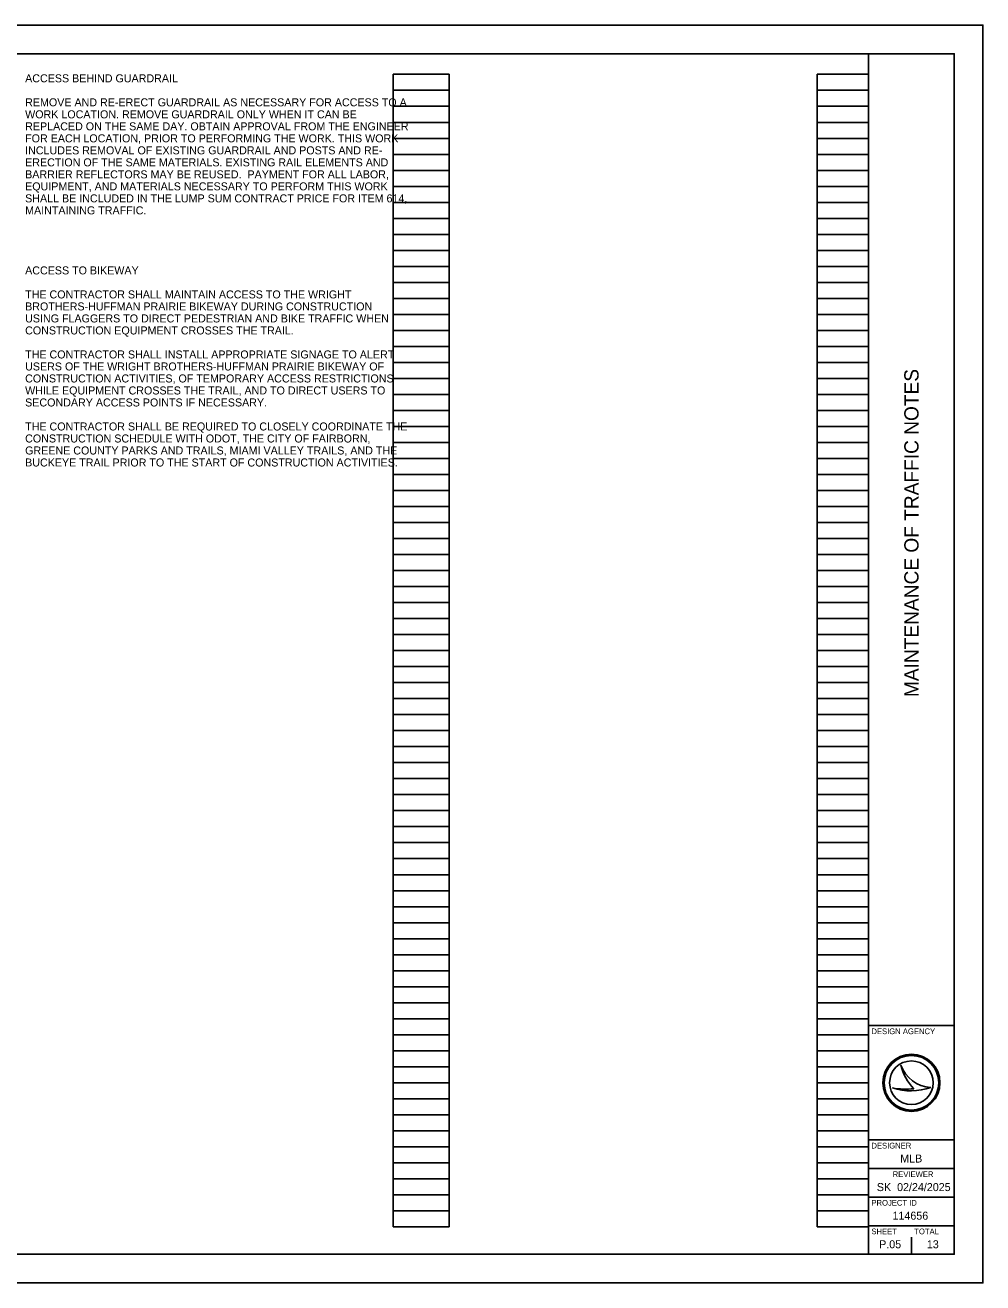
# Model space of a CAD drawing. Extents: x 0 to 34, y 0 to 22.
# Drawn here: x 17.24 to 34, y 0 to 22 of the extents above; entities that cross this region are included whole.
import ezdxf

# ---------------------------------------------------------------- set-up
doc = ezdxf.new("R2010")
doc.units = 0
for name, color, linetype in [('SH_Border', 7, 'Continuous'), ('SH_Cut_Line', 7, 'Continuous'), ('SH_Data', 7, 'Continuous'), ('SH_Text', 7, 'Continuous')]:
    doc.layers.add(name, color=color, linetype=linetype)

msp = doc.modelspace()

# ---------------------------------------------------------------- linework, layer by layer
at = {"layer": 'SH_Border'}
for p, q in [((32, 0.5), (32, 21.5)), ((32, 4.5), (33.5, 4.5)), ((32, 2.5), (33.5, 2.5)), ((32, 2), (33.5, 2)), ((32, 1.5), (33.5, 1.5)), ((32, 1), (33.5, 1))]:
    msp.add_line(p, q, dxfattribs=at)
msp.add_lwpolyline([(1.5, 21.5), (33.5, 21.5), (33.5, 0.5), (1.5, 0.5)], close=True, dxfattribs=at)
at = {"layer": 'SH_Cut_Line'}
msp.add_lwpolyline([(0, 0), (34, 0), (34, 22), (0, 22)], close=True, dxfattribs=at)
at = {"layer": 'SH_Data'}
for p, q in [((23.68, 0.98), (23.68, 21.14)), ((23.68, 21.14), (24.66, 21.14)), ((24.66, 0.98), (24.66, 21.14)), ((31.1, 0.98), (31.1, 21.14)), ((31.1, 21.14), (32, 21.14)), ((32, 0.98), (32, 21.14)), ((23.68, 20.86), (24.66, 20.86)), ((31.1, 20.86), (32, 20.86)), ((23.68, 20.58), (24.66, 20.58)), ((31.1, 20.58), (32, 20.58)), ((23.68, 20.3), (24.66, 20.3)), ((31.1, 20.3), (32, 20.3)), ((23.68, 20.02), (24.66, 20.02)), ((31.1, 20.02), (32, 20.02)), ((23.68, 19.74), (24.66, 19.74)), ((31.1, 19.74), (32, 19.74)), ((23.68, 19.46), (24.66, 19.46)), ((31.1, 19.46), (32, 19.46)), ((23.68, 19.18), (24.66, 19.18)), ((31.1, 19.18), (32, 19.18)), ((23.68, 18.9), (24.66, 18.9)), ((31.1, 18.9), (32, 18.9)), ((23.68, 18.62), (24.66, 18.62)), ((31.1, 18.62), (32, 18.62)), ((23.68, 18.34), (24.66, 18.34)), ((31.1, 18.34), (32, 18.34)), ((23.68, 18.06), (24.66, 18.06)), ((31.1, 18.06), (32, 18.06)), ((23.68, 17.78), (24.66, 17.78)), ((31.1, 17.78), (32, 17.78)), ((23.68, 17.5), (24.66, 17.5)), ((31.1, 17.5), (32, 17.5)), ((23.68, 17.22), (24.66, 17.22)), ((31.1, 17.22), (32, 17.22)), ((23.68, 16.94), (24.66, 16.94)), ((31.1, 16.94), (32, 16.94)), ((23.68, 16.66), (24.66, 16.66)), ((31.1, 16.66), (32, 16.66)), ((23.68, 16.38), (24.66, 16.38)), ((31.1, 16.38), (32, 16.38)), ((23.68, 16.1), (24.66, 16.1)), ((31.1, 16.1), (32, 16.1)), ((23.68, 15.82), (24.66, 15.82)), ((31.1, 15.82), (32, 15.82)), ((23.68, 15.54), (24.66, 15.54)), ((31.1, 15.54), (32, 15.54)), ((23.68, 15.26), (24.66, 15.26)), ((31.1, 15.26), (32, 15.26)), ((23.68, 14.98), (24.66, 14.98)), ((31.1, 14.98), (32, 14.98)), ((23.68, 14.7), (24.66, 14.7)), ((31.1, 14.7), (32, 14.7)), ((23.68, 14.42), (24.66, 14.42)), ((31.1, 14.42), (32, 14.42)), ((23.68, 14.14), (24.66, 14.14)), ((31.1, 14.14), (32, 14.14)), ((23.68, 13.86), (24.66, 13.86)), ((31.1, 13.86), (32, 13.86)), ((23.68, 13.58), (24.66, 13.58)), ((31.1, 13.58), (32, 13.58)), ((23.68, 13.3), (24.66, 13.3)), ((31.1, 13.3), (32, 13.3)), ((23.68, 13.02), (24.66, 13.02)), ((31.1, 13.02), (32, 13.02)), ((23.68, 12.74), (24.66, 12.74)), ((31.1, 12.74), (32, 12.74)), ((23.68, 12.46), (24.66, 12.46)), ((31.1, 12.46), (32, 12.46)), ((23.68, 12.18), (24.66, 12.18)), ((31.1, 12.18), (32, 12.18)), ((23.68, 11.9), (24.66, 11.9)), ((31.1, 11.9), (32, 11.9)), ((23.68, 11.62), (24.66, 11.62)), ((31.1, 11.62), (32, 11.62)), ((23.68, 11.34), (24.66, 11.34)), ((31.1, 11.34), (32, 11.34)), ((23.68, 11.06), (24.66, 11.06)), ((31.1, 11.06), (32, 11.06)), ((23.68, 10.78), (24.66, 10.78)), ((31.1, 10.78), (32, 10.78)), ((23.68, 10.5), (24.66, 10.5)), ((31.1, 10.5), (32, 10.5)), ((23.68, 10.22), (24.66, 10.22)), ((31.1, 10.22), (32, 10.22)), ((23.68, 9.94), (24.66, 9.94)), ((31.1, 9.94), (32, 9.94)), ((23.68, 9.66), (24.66, 9.66)), ((31.1, 9.66), (32, 9.66)), ((23.68, 9.38), (24.66, 9.38)), ((31.1, 9.38), (32, 9.38)), ((23.68, 9.1), (24.66, 9.1)), ((31.1, 9.1), (32, 9.1)), ((23.68, 8.82), (24.66, 8.82)), ((31.1, 8.82), (32, 8.82)), ((23.68, 8.54), (24.66, 8.54)), ((31.1, 8.54), (32, 8.54)), ((23.68, 8.26), (24.66, 8.26)), ((31.1, 8.26), (32, 8.26)), ((23.68, 7.98), (24.66, 7.98)), ((31.1, 7.98), (32, 7.98)), ((23.68, 7.7), (24.66, 7.7)), ((31.1, 7.7), (32, 7.7)), ((23.68, 7.42), (24.66, 7.42)), ((31.1, 7.42), (32, 7.42)), ((23.68, 7.14), (24.66, 7.14)), ((31.1, 7.14), (32, 7.14)), ((23.68, 6.86), (24.66, 6.86)), ((31.1, 6.86), (32, 6.86)), ((23.68, 6.58), (24.66, 6.58)), ((31.1, 6.58), (32, 6.58)), ((23.68, 6.3), (24.66, 6.3)), ((31.1, 6.3), (32, 6.3)), ((23.68, 6.02), (24.66, 6.02)), ((31.1, 6.02), (32, 6.02)), ((23.68, 5.74), (24.66, 5.74)), ((31.1, 5.74), (32, 5.74)), ((23.68, 5.46), (24.66, 5.46)), ((31.1, 5.46), (32, 5.46)), ((23.68, 5.18), (24.66, 5.18)), ((31.1, 5.18), (32, 5.18)), ((23.68, 4.9), (24.66, 4.9)), ((31.1, 4.9), (32, 4.9)), ((23.68, 4.62), (24.66, 4.62)), ((31.1, 4.62), (32, 4.62)), ((23.68, 4.34), (24.66, 4.34)), ((31.1, 4.34), (32, 4.34)), ((23.68, 4.06), (24.66, 4.06)), ((31.1, 4.06), (32, 4.06)), ((23.68, 3.78), (24.66, 3.78)), ((31.1, 3.78), (32, 3.78)), ((32.567, 3.81), (32.567, 3.81)), ((23.68, 3.5), (24.66, 3.5)), ((31.1, 3.5), (32, 3.5)), ((32.417, 3.41), (32.417, 3.41)), ((32.75, 3.5), (32.75, 3.5)), ((33.087, 3.419), (33.087, 3.419)), ((23.68, 3.22), (24.66, 3.22)), ((31.1, 3.22), (32, 3.22)), ((23.68, 2.94), (24.66, 2.94)), ((31.1, 2.94), (32, 2.94)), ((23.68, 2.66), (24.66, 2.66)), ((31.1, 2.66), (32, 2.66)), ((23.68, 2.38), (24.66, 2.38)), ((31.1, 2.38), (32, 2.38)), ((23.68, 2.1), (24.66, 2.1)), ((31.1, 2.1), (32, 2.1)), ((23.68, 1.82), (24.66, 1.82)), ((31.1, 1.82), (32, 1.82)), ((23.68, 1.54), (24.66, 1.54)), ((31.1, 1.54), (32, 1.54)), ((23.68, 1.26), (24.66, 1.26)), ((31.1, 1.26), (32, 1.26)), ((23.68, 0.98), (24.66, 0.98)), ((31.1, 0.98), (32, 0.98)), ((32.375, 0.675), (32.375, 0.675)), ((32.75, 0.5), (32.75, 0.8))]:
    msp.add_line(p, q, dxfattribs=at)
for radius in [0.5, 0.477, 0.477, 0.382]:
    msp.add_circle((32.75, 3.5), radius, dxfattribs=at)
for centre, radius, start, end in [((33.116, 3.998), 0.58, 198.9257, 198.9319), ((33.347, 3.97), 0.796, 191.6379, 191.6421), ((33.116, 3.998), 0.58, 198.9319, 267.1657), ((33.347, 3.97), 0.796, 191.6421, 226.0947), ((32.739, 4.37), 1.013, 251.4576, 290.0832), ((32.648, 4.654), 1.266, 259.4964, 259.4995), ((32.739, 4.37), 1.013, 251.4527, 251.4576), ((32.648, 4.654), 1.266, 259.4995, 276.6672)]:
    msp.add_arc(centre, radius, start, end, dxfattribs=at)

# ---------------------------------------------------------------- texts
msp.add_text('MAINTENANCE OF TRAFFIC NOTES', height=0.25, rotation=90, dxfattribs=at).set_placement((32.875, 10.247))
for s, height, p in [('DESIGN AGENCY', 0.1, (32.05, 4.35)), ('DESIGNER', 0.1, (32.05, 2.35)), ('MLB', 0.14, (32.554, 2.105)), ('REVIEWER', 0.1, (32.422, 1.85)), ('SK', 0.14, (32.145, 1.605)), ('02/24/2025', 0.14, (32.499, 1.605)), ('PROJECT ID', 0.1, (32.05, 1.35)), ('114656', 0.14, (32.419, 1.105)), ('SHEET', 0.1, (32.05, 0.85)), ('TOTAL', 0.1, (32.8, 0.85)), ('P.05', 0.14, (32.185, 0.605)), ('13', 0.14, (33.02, 0.605))]:
    msp.add_text(s, height=height, dxfattribs=at).set_placement(p)
at = {"layer": 'SH_Text'}
for s, p in [('ACCESS BEHIND GUARDRAIL', (17.24, 21)), ('REMOVE AND RE-ERECT GUARDRAIL AS NECESSARY FOR ACCESS TO A ', (17.24, 20.58)), ('WORK LOCATION. REMOVE GUARDRAIL ONLY WHEN IT CAN BE ', (17.24, 20.37)), ('REPLACED ON THE SAME DAY. OBTAIN APPROVAL FROM THE ENGINEER ', (17.24, 20.16)), ('FOR EACH LOCATION, PRIOR TO PERFORMING THE WORK. THIS WORK ', (17.24, 19.95)), ('INCLUDES REMOVAL OF EXISTING GUARDRAIL AND POSTS AND RE-', (17.24, 19.74)), ('ERECTION OF THE SAME MATERIALS. EXISTING RAIL ELEMENTS AND ', (17.24, 19.53)), ('BARRIER REFLECTORS MAY BE REUSED.  PAYMENT FOR ALL LABOR, ', (17.24, 19.32)), ('EQUIPMENT, AND MATERIALS NECESSARY TO PERFORM THIS WORK ', (17.24, 19.11)), ('SHALL BE INCLUDED IN THE LUMP SUM CONTRACT PRICE FOR ITEM 614, ', (17.24, 18.9)), ('MAINTAINING TRAFFIC.', (17.24, 18.69)), ('ACCESS TO BIKEWAY', (17.24, 17.64)), ('THE CONTRACTOR SHALL MAINTAIN ACCESS TO THE WRIGHT ', (17.24, 17.22)), ('USING FLAGGERS TO DIRECT PEDESTRIAN AND BIKE TRAFFIC WHEN ', (17.24, 16.8)), ('BROTHERS-HUFFMAN PRAIRIE BIKEWAY DURING CONSTRUCTION ', (17.24, 17.01)), ('CONSTRUCTION EQUIPMENT CROSSES THE TRAIL.', (17.24, 16.59)), ('THE CONTRACTOR SHALL INSTALL APPROPRIATE SIGNAGE TO ALERT ', (17.24, 16.17)), ('USERS OF THE WRIGHT BROTHERS-HUFFMAN PRAIRIE BIKEWAY OF ', (17.24, 15.96)), ('CONSTRUCTION ACTIVITIES, OF TEMPORARY ACCESS RESTRICTIONS ', (17.24, 15.75)), ('WHILE EQUIPMENT CROSSES THE TRAIL, AND TO DIRECT USERS TO ', (17.24, 15.54)), ('SECONDARY ACCESS POINTS IF NECESSARY.', (17.24, 15.33)), ('THE CONTRACTOR SHALL BE REQUIRED TO CLOSELY COORDINATE THE ', (17.24, 14.91)), ('CONSTRUCTION SCHEDULE WITH ODOT, THE CITY OF FAIRBORN, ', (17.24, 14.7)), ('GREENE COUNTY PARKS AND TRAILS, MIAMI VALLEY TRAILS, AND THE ', (17.24, 14.49)), ('BUCKEYE TRAIL PRIOR TO THE START OF CONSTRUCTION ACTIVITIES.', (17.24, 14.28))]:
    msp.add_text(s, height=0.14, dxfattribs=at).set_placement(p)

doc.saveas('drawing.dxf')
